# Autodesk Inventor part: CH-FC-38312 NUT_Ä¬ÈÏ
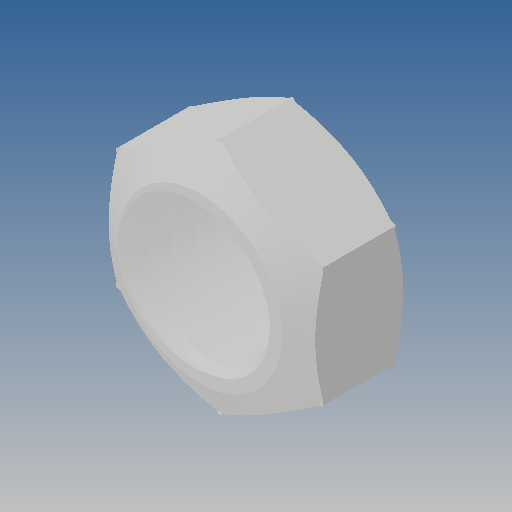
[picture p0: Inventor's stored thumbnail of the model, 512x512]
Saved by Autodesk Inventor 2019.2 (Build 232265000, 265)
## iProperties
Created: 2012-09
Part Number: CH-FC-38312 NUT_Ä¬ÈÏ
Material: Ogólny
Document SubType Name: Modeling
Designer: CADENGINEERING4
Density: 1 g/cm^3
Appearance: Domyślna
Author: CADENGINEERING4
Revision Number: ÈÎºÎ
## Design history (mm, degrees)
feature "NONE"
node "Bryła1"
